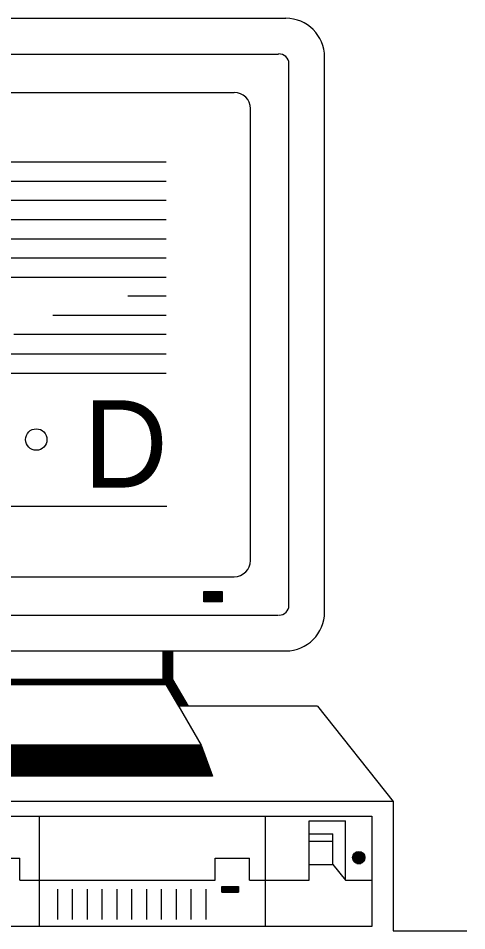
# Model space of a CAD drawing. Extents: x 0 to 53.3, y -2.9 to 37.3.
# Drawn here: x 23.9514 to 24.0151, y -2.7946 to -2.665 of the extents above; entities that cross this region are included whole.
import ezdxf

# ---------------------------------------------------------------- set-up
doc = ezdxf.new("R2010")
doc.units = 0
for name, color, linetype in [('Level 1', 7, 'Continuous'), ('Level 25', 7, 'Continuous'), ('Level 50', 7, 'Continuous')]:
    doc.layers.add(name, color=color, linetype=linetype)

msp = doc.modelspace()

# ---------------------------------------------------------------- linework, layer by layer
at = {"layer": 'Level 1'}
for p, q in [((23.91345, -2.68543), (23.9724, -2.68543)), ((23.94836, -2.68816), (23.9724, -2.68816)), ((23.94836, -2.69088), (23.9724, -2.69088)), ((23.94836, -2.6936), (23.9724, -2.6936)), ((23.94836, -2.69633), (23.9724, -2.69633)), ((23.94836, -2.69906), (23.9724, -2.69906)), ((23.91345, -2.70179), (23.9724, -2.70179)), ((23.97239, -2.70449), (23.96695, -2.70449)), ((23.97239, -2.70722), (23.95633, -2.70722)), ((23.97239, -2.70994), (23.95075, -2.70994)), ((23.91345, -2.71267), (23.9724, -2.71267)), ((23.91345, -2.7154), (23.9724, -2.7154)), ((23.91345, -2.73431), (23.97251, -2.73431))]:
    msp.add_line(p, q, dxfattribs=at)
msp.add_circle((23.95395, -2.72483), 0.00152, dxfattribs=at)
at = {"layer": 'Level 25'}
for p, q in [((23.9949, -2.74934), (23.9949, -2.67054)), ((23.98983, -2.74838), (23.98983, -2.67148)), ((23.98437, -2.74202), (23.98437, -2.67786)), ((23.90323, -2.74431), (23.98208, -2.74431)), ((23.97776, -2.74646), (23.98037, -2.74646)), ((23.97776, -2.74654), (23.98037, -2.74654)), ((23.97776, -2.74662), (23.98037, -2.74662)), ((23.97776, -2.74671), (23.98037, -2.74671)), ((23.97776, -2.7468), (23.98037, -2.7468)), ((23.97776, -2.74687), (23.98037, -2.74687)), ((23.97776, -2.74695), (23.98037, -2.74695)), ((23.97776, -2.74704), (23.98037, -2.74704)), ((23.97776, -2.74712), (23.98037, -2.74712)), ((23.97776, -2.7472), (23.98037, -2.7472)), ((23.97776, -2.74729), (23.98037, -2.74729)), ((23.97776, -2.74737), (23.98037, -2.74737)), ((23.97776, -2.74744), (23.98037, -2.74744)), ((23.97776, -2.74754), (23.98037, -2.74754)), ((23.97776, -2.74762), (23.98037, -2.74762)), ((23.97776, -2.74769), (23.98037, -2.74769)), ((23.97776, -2.74778), (23.98037, -2.74778)), ((23.89685, -2.74975), (23.98836, -2.74975)), ((23.8959, -2.75484), (23.9894, -2.75484)), ((23.97199, -2.75888), (23.97199, -2.75484)), ((23.97331, -2.75487), (23.97199, -2.75487)), ((23.97331, -2.75888), (23.97331, -2.75484)), ((23.97331, -2.75495), (23.97199, -2.75495)), ((23.97331, -2.75503), (23.97199, -2.75503)), ((23.97331, -2.75512), (23.97199, -2.75512)), ((23.97331, -2.7552), (23.97199, -2.7552)), ((23.97331, -2.75529), (23.97199, -2.75529)), ((23.97331, -2.75536), (23.97199, -2.75536)), ((23.97331, -2.75544), (23.97199, -2.75544)), ((23.97331, -2.75554), (23.97199, -2.75554)), ((23.97331, -2.75562), (23.97199, -2.75562)), ((23.97331, -2.75569), (23.97199, -2.75569)), ((23.97331, -2.75578), (23.97199, -2.75578)), ((23.97331, -2.75586), (23.97199, -2.75586)), ((23.97331, -2.75594), (23.97199, -2.75594)), ((23.97331, -2.75603), (23.97199, -2.75603)), ((23.97331, -2.75611), (23.97199, -2.75611)), ((23.97331, -2.75619), (23.97199, -2.75619)), ((23.97331, -2.75627), (23.97199, -2.75627)), ((23.97331, -2.75636), (23.97199, -2.75636)), ((23.97331, -2.75644), (23.97199, -2.75644)), ((23.97331, -2.75652), (23.97199, -2.75652)), ((23.97331, -2.7566), (23.97199, -2.7566)), ((23.97331, -2.75668), (23.97199, -2.75668)), ((23.97331, -2.75678), (23.97199, -2.75678)), ((23.97331, -2.75685), (23.97199, -2.75685)), ((23.97331, -2.75693), (23.97199, -2.75693)), ((23.97331, -2.75702), (23.97199, -2.75702)), ((23.97331, -2.75709), (23.97199, -2.75709)), ((23.97331, -2.75718), (23.97199, -2.75718)), ((23.97331, -2.75727), (23.97199, -2.75727)), ((23.97331, -2.75735), (23.97199, -2.75735)), ((23.97331, -2.75742), (23.97199, -2.75742)), ((23.97331, -2.7575), (23.97199, -2.7575)), ((23.97331, -2.7576), (23.97199, -2.7576)), ((23.97331, -2.75768), (23.97199, -2.75768)), ((23.97331, -2.75775), (23.97199, -2.75775)), ((23.97331, -2.75784), (23.97199, -2.75784)), ((23.97331, -2.75792), (23.97199, -2.75792)), ((23.97331, -2.758), (23.97199, -2.758)), ((23.97331, -2.75809), (23.97199, -2.75809)), ((23.97331, -2.75817), (23.97199, -2.75817)), ((23.97331, -2.75825), (23.97199, -2.75825)), ((23.97331, -2.75833), (23.97199, -2.75833)), ((23.97331, -2.75842), (23.97199, -2.75842)), ((23.97331, -2.7585), (23.97199, -2.7585)), ((23.97331, -2.75858), (23.97199, -2.75858)), ((23.97331, -2.75866), (23.97199, -2.75866)), ((23.97331, -2.75874), (23.97199, -2.75874)), ((23.97199, -2.75888), (23.94265, -2.75888)), ((23.97201, -2.7589), (23.94265, -2.7589)), ((23.97206, -2.75898), (23.94265, -2.75898)), ((23.9721, -2.75907), (23.94265, -2.75907)), ((23.97214, -2.75915), (23.94265, -2.75915)), ((23.9722, -2.75923), (23.94265, -2.75923)), ((23.97224, -2.75932), (23.94265, -2.75932)), ((23.97229, -2.7594), (23.94265, -2.7594)), ((23.97234, -2.75947), (23.94265, -2.75947)), ((23.97239, -2.75957), (23.94265, -2.75957)), ((23.97244, -2.75965), (23.94265, -2.75965)), ((23.97245, -2.75966), (23.94265, -2.75966)), ((23.97331, -2.75884), (23.97199, -2.75884)), ((23.97199, -2.75888), (23.97735, -2.76822)), ((23.97333, -2.75891), (23.97201, -2.75891)), ((23.97337, -2.75899), (23.97206, -2.75899)), ((23.97344, -2.75908), (23.9721, -2.75908)), ((23.97348, -2.75915), (23.97216, -2.75915)), ((23.97352, -2.75924), (23.97221, -2.75924)), ((23.97357, -2.75933), (23.97225, -2.75933)), ((23.97361, -2.75941), (23.9723, -2.75941)), ((23.97366, -2.75948), (23.97234, -2.75948)), ((23.97372, -2.75957), (23.97239, -2.75957)), ((23.97375, -2.75966), (23.97244, -2.75966)), ((23.97381, -2.75974), (23.97248, -2.75974)), ((23.97385, -2.75982), (23.97254, -2.75982)), ((23.9739, -2.7599), (23.97258, -2.7599)), ((23.97395, -2.75998), (23.97263, -2.75998)), ((23.974, -2.76007), (23.97267, -2.76007)), ((23.97331, -2.75888), (23.97551, -2.76269)), ((23.97404, -2.76015), (23.97272, -2.76015)), ((23.97409, -2.76023), (23.97277, -2.76023)), ((23.97414, -2.76032), (23.97282, -2.76032)), ((23.97419, -2.76039), (23.97286, -2.76039)), ((23.97424, -2.76048), (23.97291, -2.76048)), ((23.97428, -2.76057), (23.97297, -2.76057)), ((23.97432, -2.76064), (23.97301, -2.76064)), ((23.97437, -2.76072), (23.97305, -2.76072)), ((23.97441, -2.76081), (23.9731, -2.76081)), ((23.97448, -2.7609), (23.97314, -2.7609)), ((23.97452, -2.76097), (23.97321, -2.76097)), ((23.97457, -2.76106), (23.97325, -2.76106)), ((23.97461, -2.76114), (23.97329, -2.76114)), ((23.97465, -2.76121), (23.97334, -2.76121)), ((23.97471, -2.76131), (23.97338, -2.76131)), ((23.97475, -2.76139), (23.97344, -2.76139)), ((23.9748, -2.76147), (23.97348, -2.76147)), ((23.97485, -2.76155), (23.97352, -2.76155)), ((23.97489, -2.76163), (23.97358, -2.76163)), ((23.97495, -2.76172), (23.97362, -2.76172)), ((23.97499, -2.76181), (23.97367, -2.76181)), ((23.97504, -2.76188), (23.97372, -2.76188)), ((23.97508, -2.76196), (23.97377, -2.76196)), ((23.97512, -2.76205), (23.97381, -2.76205)), ((23.97519, -2.76213), (23.97385, -2.76213)), ((23.97523, -2.76221), (23.9739, -2.76221)), ((23.97528, -2.7623), (23.97396, -2.7623)), ((23.97532, -2.76238), (23.97401, -2.76238)), ((23.97537, -2.76245), (23.97405, -2.76245)), ((23.97541, -2.76255), (23.97409, -2.76255)), ((23.97546, -2.76263), (23.97414, -2.76263)), ((23.99391, -2.76269), (24.00462, -2.7762)), ((23.97736, -2.76825), (23.94265, -2.76825)), ((23.97739, -2.76834), (23.94265, -2.76834)), ((23.97744, -2.76841), (23.94265, -2.76841)), ((23.97746, -2.7685), (23.94265, -2.7685)), ((23.97749, -2.76859), (23.94265, -2.76859)), ((23.97752, -2.76866), (23.94265, -2.76866)), ((23.97755, -2.76874), (23.94265, -2.76874)), ((23.97758, -2.76883), (23.94265, -2.76883)), ((23.9776, -2.76892), (23.94265, -2.76892)), ((23.97763, -2.76899), (23.94265, -2.76899)), ((23.97767, -2.76908), (23.94265, -2.76908)), ((23.97771, -2.76916), (23.94265, -2.76916)), ((23.97773, -2.76923), (23.94265, -2.76923)), ((23.97776, -2.76933), (23.94265, -2.76933)), ((23.9778, -2.76941), (23.94265, -2.76941)), ((23.97782, -2.76949), (23.94265, -2.76949)), ((23.97785, -2.76957), (23.94265, -2.76957)), ((23.97787, -2.76965), (23.94265, -2.76965)), ((23.97791, -2.76974), (23.94265, -2.76974)), ((23.97795, -2.76983), (23.94265, -2.76983)), ((23.97798, -2.7699), (23.94265, -2.7699)), ((23.97801, -2.76998), (23.94265, -2.76998)), ((23.97804, -2.77007), (23.94265, -2.77007)), ((23.97806, -2.77015), (23.94265, -2.77015)), ((23.97809, -2.77023), (23.94265, -2.77023)), ((23.97813, -2.77032), (23.94265, -2.77032)), ((23.97815, -2.7704), (23.94265, -2.7704)), ((23.97819, -2.77047), (23.94265, -2.77047)), ((23.97822, -2.77057), (23.94265, -2.77057)), ((23.97826, -2.77065), (23.94265, -2.77065)), ((23.97828, -2.77072), (23.94265, -2.77072)), ((23.97831, -2.77081), (23.94265, -2.77081)), ((23.97833, -2.77089), (23.94265, -2.77089)), ((23.97837, -2.77098), (23.94265, -2.77098)), ((23.9784, -2.77106), (23.94265, -2.77106)), ((23.97842, -2.77114), (23.94265, -2.77114)), ((23.97847, -2.77122), (23.94265, -2.77122)), ((23.9785, -2.7713), (23.94265, -2.7713)), ((23.97852, -2.77139), (23.94265, -2.77139)), ((23.97855, -2.77147), (23.94265, -2.77147)), ((23.97859, -2.77156), (23.94265, -2.77156)), ((23.97861, -2.77163), (23.94265, -2.77163)), ((23.97864, -2.77171), (23.94265, -2.77171)), ((23.97867, -2.77181), (23.94265, -2.77181)), ((23.97871, -2.77189), (23.94265, -2.77189)), ((23.97874, -2.77196), (23.94265, -2.77196)), ((23.97877, -2.77205), (23.94265, -2.77205)), ((23.97879, -2.77213), (23.94265, -2.77213)), ((23.97883, -2.77221), (23.94265, -2.77221)), ((23.97886, -2.7723), (23.94265, -2.7723)), ((23.97888, -2.77238), (23.94265, -2.77238)), ((23.97892, -2.77246), (23.94265, -2.77246)), ((23.97896, -2.77254), (23.94265, -2.77254)), ((24.00462, -2.7762), (23.94265, -2.7762)), ((24.00462, -2.7762), (24.00462, -2.79456)), ((23.95442, -2.79395), (23.95442, -2.77828)), ((23.98652, -2.79395), (23.98652, -2.77828)), ((23.99272, -2.78736), (23.99272, -2.77895)), ((23.99272, -2.77895), (23.99789, -2.77895)), ((23.99789, -2.78736), (23.99789, -2.77895)), ((23.99272, -2.78078), (23.99606, -2.78078)), ((23.99606, -2.78514), (23.99606, -2.78078)), ((23.99272, -2.78183), (23.99606, -2.78183)), ((23.9995, -2.78335), (24.00003, -2.78335)), ((23.94545, -2.78427), (23.95162, -2.78427)), ((23.95162, -2.78736), (23.95162, -2.78427)), ((23.97938, -2.78427), (23.98422, -2.78427)), ((23.97938, -2.78736), (23.97938, -2.78427)), ((23.98422, -2.78736), (23.98422, -2.78427)), ((23.99888, -2.78417), (24.00063, -2.78417)), ((23.99889, -2.78408), (24.00062, -2.78408)), ((23.99889, -2.78424), (24.00063, -2.78424)), ((23.9989, -2.78399), (24.00061, -2.78399)), ((23.9989, -2.78433), (24.00061, -2.78433)), ((23.99891, -2.78441), (24.0006, -2.78441)), ((23.99892, -2.78392), (24.0006, -2.78392)), ((23.99895, -2.78384), (24.00056, -2.78384)), ((23.99895, -2.78449), (24.00056, -2.78449)), ((23.99899, -2.78458), (24.00053, -2.78458)), ((23.999, -2.78375), (24.00053, -2.78375)), ((23.99903, -2.78466), (24.00049, -2.78466)), ((23.99904, -2.78366), (24.00048, -2.78366)), ((23.99911, -2.78359), (24.0004, -2.78359)), ((23.99919, -2.7835), (24.00032, -2.7835)), ((23.9993, -2.78342), (24.00021, -2.78342)), ((23.99272, -2.78514), (23.99606, -2.78514)), ((23.99606, -2.78514), (23.99789, -2.78736)), ((23.9991, -2.78474), (24.00041, -2.78474)), ((23.99917, -2.78482), (24.00033, -2.78482)), ((23.99929, -2.7849), (24.00024, -2.7849)), ((23.99946, -2.78499), (24.00006, -2.78499)), ((23.95162, -2.78736), (23.97935, -2.78736)), ((23.98033, -2.78828), (23.98269, -2.78828)), ((23.98033, -2.78835), (23.98269, -2.78835)), ((23.98033, -2.78844), (23.98269, -2.78844)), ((23.98033, -2.78853), (23.98269, -2.78853)), ((23.98422, -2.78736), (23.99272, -2.78736)), ((23.99789, -2.78736), (24.00162, -2.78736)), ((23.95701, -2.79295), (23.95701, -2.78864)), ((23.95911, -2.79295), (23.95911, -2.78864)), ((23.96122, -2.79295), (23.96122, -2.78864)), ((23.96332, -2.79295), (23.96332, -2.78864)), ((23.96544, -2.79295), (23.96544, -2.78864)), ((23.96754, -2.79295), (23.96754, -2.78864)), ((23.96965, -2.79295), (23.96965, -2.78864)), ((23.97176, -2.79295), (23.97176, -2.78864)), ((23.97385, -2.79295), (23.97385, -2.78864)), ((23.97597, -2.79295), (23.97597, -2.78864)), ((23.97807, -2.79295), (23.97807, -2.78864)), ((23.98033, -2.7886), (23.98269, -2.7886)), ((23.98033, -2.78868), (23.98269, -2.78868)), ((23.98033, -2.78877), (23.98269, -2.78877)), ((23.98033, -2.78886), (23.98269, -2.78886)), ((23.98033, -2.78893), (23.98269, -2.78893)), ((23.98033, -2.78902), (23.98269, -2.78902)), ((23.98033, -2.7891), (23.98269, -2.7891)), ((24.00462, -2.79456), (24.01509, -2.79456))]:
    msp.add_line(p, q, dxfattribs=at)
for points in [[(23.97776, -2.7464), (23.98037, -2.7464), (23.98037, -2.74785), (23.97776, -2.74785)], [(23.97331, -2.75484), (23.97331, -2.75888), (23.97551, -2.76269), (23.97419, -2.76269), (23.97199, -2.75888), (23.97199, -2.75484)], [(23.97199, -2.75888), (23.97245, -2.75966), (23.94265, -2.75966), (23.94265, -2.75888)], [(23.97735, -2.76822), (23.97898, -2.77261), (23.94265, -2.77261), (23.94265, -2.76822)], [(23.88387, -2.77828), (24.00162, -2.77828), (24.00162, -2.79395), (23.88387, -2.79395)], [(23.98033, -2.78828), (23.98269, -2.78828), (23.98269, -2.7891), (23.98033, -2.7891)]]:
    msp.add_lwpolyline(points, close=True, dxfattribs=at)
msp.add_circle((23.99976, -2.78417), 0.000875, dxfattribs=at)
for centre, start, end in [((23.98845, -2.67148), 0, 93.8704), ((23.98845, -2.74838), 270, 0)]:
    msp.add_arc(centre, 0.00138, start, end, dxfattribs=at)
at = {"layer": 'Level 50'}
for p, q in [((23.8959, -2.66504), (23.9894, -2.66504)), ((23.89685, -2.67011), (23.98836, -2.67011)), ((23.90323, -2.67557), (23.98208, -2.67557)), ((23.99391, -2.76269), (23.97419, -2.76269)), ((23.97735, -2.76822), (23.94265, -2.76822)), ((23.97898, -2.77261), (23.94265, -2.77261))]:
    msp.add_line(p, q, dxfattribs=at)
for centre, radius, start, end in [((23.9894, -2.67054), 0.0055, 0, 90), ((23.98208, -2.67786), 0.00229, 0, 90), ((23.98208, -2.74201), 0.00229, 270, 0), ((23.9894, -2.74933), 0.0055, 270, 0)]:
    msp.add_arc(centre, radius, start, end, dxfattribs=at)

# ---------------------------------------------------------------- texts
at = {"layer": 'Level 1'}
msp.add_text('D', height=0.0124, dxfattribs=at).set_placement((23.96066, -2.73165))

doc.saveas('drawing.dxf')
